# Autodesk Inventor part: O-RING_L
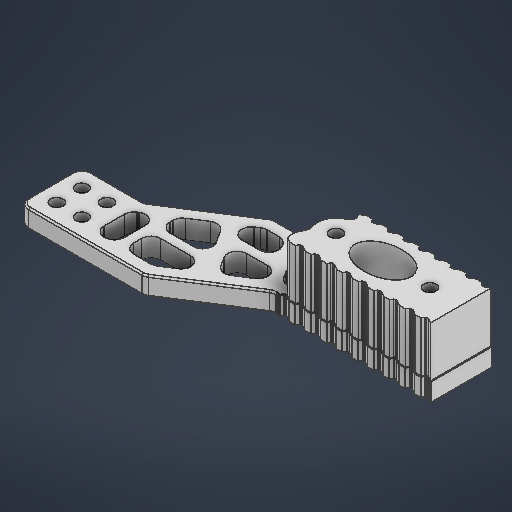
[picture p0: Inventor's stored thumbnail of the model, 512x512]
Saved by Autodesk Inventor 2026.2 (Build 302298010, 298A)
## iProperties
Created: 2026-05
Part Number: O-RING_L
Material: 일반
Document SubType Name: Modeling
Designer: work
Density: 1 g/cm^3
Appearance: 기본값
Author: work
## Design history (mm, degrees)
sketch "스케치1"
  geometry: L1 (0, 22)-(0, -22); L2 (0, -22)-(8, -22); L3 (8, -22)-(8, -30); L4 (8, -30)-(0, -30); L5 (0, -30)-(0, -22); L6 (0, -22)-(8, -30); L7 (8, -22)-(0, -30); L8 (-6, -36)-(14, -36); L9 (14, -36)-(14, -16); L10 (14, -16)-(-6, -16); L11 (-6, -16)-(-6, -36); L12 (-6, -36)-(14, -16); L13 (14, -36)-(-6, -16); L14 (-6, -16)-(-31, 0); L15 (-101, 0)-(-101, -20); L16 (-6, -36)-(-26, -36); L17 (-26, -36)-(-51, -20); L18 (0, 0)-(-31, 0); L19 (-101, -10)-(-15.375, -10); L20 (-101, 0)-(-99.268, -1); L21 (-99.268, -1)-(-98.577, -1); L22 (-98.577, -1)-(-98, 0); L23 (-93.577, -1)-(-93, 0); L24 (-94.268, -1)-(-93.577, -1); L25 (-96, 0)-(-94.268, -1); L26 (-88.577, -1)-(-88, 0); L27 (-89.268, -1)-(-88.577, -1); L28 (-91, 0)-(-89.268, -1); L29 (-83.577, -1)-(-83, 0); L30 (-84.268, -1)-(-83.577, -1); L31 (-86, 0)-(-84.268, -1); L32 (-78.577, -1)-(-78, 0); L33 (-79.268, -1)-(-78.577, -1); L34 (-81, 0)-(-79.268, -1); L35 (-73.577, -1)-(-73, 0); L36 (-74.268, -1)-(-73.577, -1); L37 (-76, 0)-(-74.268, -1); L38 (-68.577, -1)-(-68, 0); L39 (-69.268, -1)-(-68.577, -1); L40 (-71, 0)-(-69.268, -1); L41 (-63.577, -1)-(-63, 0); L42 (-64.268, -1)-(-63.577, -1); L43 (-66, 0)-(-64.268, -1); L44 (-58.577, -1)-(-58, 0); L45 (-59.268, -1)-(-58.577, -1); L46 (-61, 0)-(-59.268, -1); L47 (-53.577, -1)-(-53, 0); L48 (-54.268, -1)-(-53.577, -1); L49 (-56, 0)-(-54.268, -1); L50 (-73.577, -19)-(-73, -20); L51 (-74.268, -19)-(-73.577, -19); L52 (-76, -20)-(-74.268, -19); L53 (-78.577, -19)-(-78, -20); L54 (-79.268, -19)-(-78.577, -19); L55 (-81, -20)-(-79.268, -19); L56 (-83.577, -19)-(-83, -20); L57 (-84.268, -19)-(-83.577, -19); L58 (-86, -20)-(-84.268, -19); L59 (-71, -20)-(-69.268, -19); L60 (-69.268, -19)-(-68.577, -19); L61 (-68.577, -19)-(-68, -20); L62 (-66, -20)-(-64.268, -19); L63 (-64.268, -19)-(-63.577, -19); L64 (-63.577, -19)-(-63, -20)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; C1 r 2 at (-91, -10); C2 r 2 at (-61, -10); 48 further points; 1 other entity
  constraints: 194 end point, 39 symmetric about line, 38 horizontal alignment, 30 parallel, 26 point on line, 11 midpoint, 9 collinear, 9 horizontal, 8 perpendicular, 6 coincident, 4 vertical, 2 centre point, 17 other
  dimensions: "d0" = 44 distance of L1.start L1.end; "d1" = 8 distance of L3.end L4.end; "d2" = 8 distance of L2.end L3.end; "d3" = 6 distance between parallel lines of L2 L10; "d5" = 50 distance from line of L17.end L15; "d6" = 20 distance of L8.start L16.end; "d7" = 25 horizontal distance of L14.end L10.end; "d8" = 20 distance of L15.start L15.end; "d9" = 3 distance of L15.start L22.end; "d10" = 30 deg angle to the sketch x axis of L20; "d11" = 1 distance of the line from the sketch origin of L21; "d14" = 5 distance of L21.end L23.start; "d19" = 4 diameter of C1; "d20" = 4 diameter of C2; "d21" = 30 distance of C1.centre C2.centre; "d22" = 10 distance from line of L15 C1.centre; "d23" = 4 distance between parallel lines of L14 L80; "d24" = 4 distance between parallel lines of L16 L82; "d25" = 3 distance between parallel lines of L90 L86; "d26" = 3 distance between parallel lines of L91 L92; "d27" = 3 distance from line of point (-32.04, -15.735) L89; "d28" = 3 distance between parallel lines of L94 L93; "d29" = 3 distance between parallel lines of L87 L88; "d30" = 3 distance between parallel lines of L95 L96
  node "스케치 - 직사각형 패턴1" dims "d14" = 5, "d17" = 10
extrude "돌출1" new body sketch "스케치1" distance "d31" = 6; taper "d32" = 0 deg
hole "구멍1" sketch "스케치1" diameter "d33" = 4; stored, may be unused: countersink angle "d37" = 90 deg, drill point angle "d39" = 118 deg; dims "d34" = 6, "d35" = 6.2, "d36" = 3, "d38" = 8
sketch "스케치2"
  geometry: C1 r 2 at (61, -10) reference; C2 r 2 at (91, -10) reference; 3 further points
  constraints: 2 coincident
hole "구멍2" sketch "스케치2" at (61, -10), (91, -10) diameter "d40" = 4; stored, may be unused: countersink angle "d44" = 90 deg, drill point angle "d46" = 118 deg; dims "d41" = 6, "d42" = 6.2, "d43" = 3, "d45" = 8
fillet "모깎기1" dims "d47" = 3
fillet "모깎기2" dims "d48" = 0.2
sketch "스케치3"
  geometry: L1 (51.878, -20)-(52.378, -20); L2 (52.378, -20)-(52.378, -19.5); L3 (52.378, -19.5)-(51.878, -19.5); L4 (51.878, -19.5)-(51.878, -20); L5 (51.878, -0.5)-(52.378, -0.5); L6 (52.378, -0.5)-(52.378, 0); L7 (52.378, 0)-(51.878, 0); L8 (51.878, 0)-(51.878, -0.5); L9 (31.878, 0)-(52.885, 0) reference; L10 (52.378, -19.5)-(52.378, -0.5); A1 r 3 centre (51.878, -23) between (51.878, -20) and (50.261, -20.473) reference; 1 further point
  constraints: 18 end point, 4 parallel, 2 horizontal, 2 perpendicular, 1 point on line, 1 vertical
  dimensions: "d49" = 0.5 distance of L3.end L2.end; "d50" = 0.5 distance of L2.end L1.end; "d51" = 0.5 distance of L7.end L6.end; "d52" = 0.5 distance of L6.end L5.end
extrude "돌출2" cut sketch "스케치3" extent not by distance; stored distance "d53" = 0; taper "d54" = 0 deg
chamfer "모따기1" distance "d55" = 0.5; stored, may be unused: second distance "d56" = 2, angle "d57" = 45 deg
chamfer "모따기2" distance "d58" = 0.2; stored, may be unused: second distance "d59" = 2, angle "d60" = 45 deg
node "작업 평면1"
sketch "스케치4"
  geometry: L1 (-37.502, -103.645)-(133.146, -103.645); L2 (133.146, -103.645)-(133.146, 10.321); L3 (133.146, 10.321)-(-37.502, 10.321); L4 (-37.502, 10.321)-(-37.502, -103.645); 1 further point
  constraints: 8 end point, 2 parallel, 1 horizontal, 1 perpendicular
extrude "돌출3" cut sketch "스케치4" extent not by distance; stored distance "d62" = 0; taper "d63" = 0 deg
sketch "스케치5"
  geometry: L1 (63.378, 15.7)-(63.885, 15.7) reference; L2 (63.885, 15.7)-(64.346, 16.5) reference; L3 (64.693, 16.7)-(65.214, 16.7) reference; L4 (65.414, 16.646)-(67.054, 15.7) reference; L5 (67.054, 15.7)-(68.885, 15.7) reference; L6 (68.885, 15.7)-(69.346, 16.5) reference; L7 (69.693, 16.7)-(70.214, 16.7) reference; L8 (70.414, 16.646)-(72.054, 15.7) reference; L9 (72.054, 15.7)-(73.885, 15.7) reference; L10 (73.885, 15.7)-(74.346, 16.5) reference; L11 (74.693, 16.7)-(75.214, 16.7) reference; L12 (75.414, 16.646)-(77.054, 15.7) reference; L13 (77.054, 15.7)-(78.885, 15.7) reference; L14 (78.885, 15.7)-(79.346, 16.5) reference; L15 (79.693, 16.7)-(80.214, 16.7) reference; L16 (80.414, 16.646)-(82.054, 15.7) reference; L17 (82.054, 15.7)-(83.885, 15.7) reference; L18 (83.885, 15.7)-(84.346, 16.5) reference; L19 (84.693, 16.7)-(85.214, 16.7) reference; L20 (85.414, 16.646)-(87.054, 15.7) reference; L21 (87.054, 15.7)-(88.885, 15.7) reference; L22 (88.885, 15.7)-(89.346, 16.5) reference; L23 (89.693, 16.7)-(90.214, 16.7) reference; L24 (90.414, 16.646)-(92.054, 15.7) reference; L25 (92.054, 15.7)-(93.885, 15.7) reference; L26 (93.885, 15.7)-(94.346, 16.5) reference; L27 (94.693, 16.7)-(95.214, 16.7) reference; L28 (95.414, 16.646)-(97.054, 15.7) reference; L29 (97.054, 15.7)-(98.885, 15.7) reference; L30 (98.885, 15.7)-(99.346, 16.5) reference; L31 (99.693, 16.7)-(100.214, 16.7) reference; L32 (100.414, 16.646)-(102.054, 15.7) reference; L33 (102.054, 15.7)-(103.885, 15.7) reference; L34 (103.885, 15.7)-(104.346, 16.5) reference; L35 (104.693, 16.7)-(105.214, 16.7) reference; L36 (105.414, 16.646)-(107.054, 15.7) reference; L37 (107.054, 15.7)-(108.885, 15.7) reference; L38 (108.885, 15.7)-(109.346, 16.5) reference; L39 (109.693, 16.7)-(110.214, 16.7) reference; L40 (110.414, 16.646)-(111.8, 15.846) reference; L41 (111.8, 15.846)-(111.8, 35.154) reference; L42 (111.8, 35.154)-(110.414, 34.354) reference; L43 (110.214, 34.3)-(109.693, 34.3) reference; L44 (109.346, 34.5)-(108.885, 35.3) reference; L45 (108.885, 35.3)-(107.054, 35.3) reference; L46 (107.054, 35.3)-(105.414, 34.354) reference; L47 (105.214, 34.3)-(104.693, 34.3) reference; L48 (104.346, 34.5)-(103.885, 35.3) reference; L49 (103.885, 35.3)-(102.054, 35.3) reference; L50 (102.054, 35.3)-(100.414, 34.354) reference; L51 (100.214, 34.3)-(99.693, 34.3) reference; L52 (99.346, 34.5)-(98.885, 35.3) reference; L53 (98.885, 35.3)-(97.054, 35.3) reference; L54 (97.054, 35.3)-(95.414, 34.354) reference; L55 (95.214, 34.3)-(94.693, 34.3) reference; L56 (94.346, 34.5)-(93.885, 35.3) reference; L57 (93.885, 35.3)-(92.054, 35.3) reference; L58 (92.054, 35.3)-(90.414, 34.354) reference; L59 (90.214, 34.3)-(89.693, 34.3) reference; L60 (89.346, 34.5)-(88.885, 35.3) reference; L61 (88.885, 35.3)-(87.054, 35.3) reference; L62 (87.054, 35.3)-(85.414, 34.354) reference; L63 (85.214, 34.3)-(84.693, 34.3) reference; L64 (84.346, 34.5)-(83.885, 35.3) reference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; C1 r 2 at (11, 13.5) reference; C2 r 2 at (3, 13.5) reference; C3 r 2 at (3, 5.5) reference; C4 r 2 at (11, 5.5) reference; C5 r 10 at (87, 25.5) reference; C6 r 2 at (72, 25.5) reference; C7 r 2 at (102, 25.5) reference; A1 r 0.4 centre (64.693, 16.3) between (64.693, 16.7) and (64.346, 16.5) reference; A2 r 0.4 centre (65.214, 16.3) between (65.414, 16.646) and (65.214, 16.7) reference; A3 r 0.4 centre (69.693, 16.3) between (69.693, 16.7) and (69.346, 16.5) reference; A4 r 0.4 centre (70.214, 16.3) between (70.414, 16.646) and (70.214, 16.7) reference; A5 r 0.4 centre (74.693, 16.3) between (74.693, 16.7) and (74.346, 16.5) reference; A6 r 0.4 centre (75.214, 16.3) between (75.414, 16.646) and (75.214, 16.7) reference; A7 r 0.4 centre (79.693, 16.3) between (79.693, 16.7) and (79.346, 16.5) reference; A8 r 0.4 centre (80.214, 16.3) between (80.414, 16.646) and (80.214, 16.7) reference; A9 r 0.4 centre (84.693, 16.3) between (84.693, 16.7) and (84.346, 16.5) reference; A10 r 0.4 centre (85.214, 16.3) between (85.414, 16.646) and (85.214, 16.7) reference; A11 r 0.4 centre (89.693, 16.3) between (89.693, 16.7) and (89.346, 16.5) reference; A12 r 0.4 centre (90.214, 16.3) between (90.414, 16.646) and (90.214, 16.7) reference; A13 r 0.4 centre (94.693, 16.3) between (94.693, 16.7) and (94.346, 16.5) reference; A14 r 0.4 centre (95.214, 16.3) between (95.414, 16.646) and (95.214, 16.7) reference; A15 r 0.4 centre (99.693, 16.3) between (99.693, 16.7) and (99.346, 16.5) reference; A16 r 0.4 centre (100.214, 16.3) between (100.414, 16.646) and (100.214, 16.7) reference; A17 r 0.4 centre (104.693, 16.3) between (104.693, 16.7) and (104.346, 16.5) reference; A18 r 0.4 centre (105.214, 16.3) between (105.414, 16.646) and (105.214, 16.7) reference; A19 r 0.4 centre (109.693, 16.3) between (109.693, 16.7) and (109.346, 16.5) reference; A20 r 0.4 centre (110.214, 16.3) between (110.414, 16.646) and (110.214, 16.7) reference; A21 r 0.4 centre (110.214, 34.7) between (110.214, 34.3) and (110.414, 34.354) reference; A22 r 0.4 centre (109.693, 34.7) between (109.346, 34.5) and (109.693, 34.3) reference; A23 r 0.4 centre (105.214, 34.7) between (105.214, 34.3) and (105.414, 34.354) reference; A24 r 0.4 centre (104.693, 34.7) between (104.346, 34.5) and (104.693, 34.3) reference; A25 r 0.4 centre (100.214, 34.7) between (100.214, 34.3) and (100.414, 34.354) reference; A26 r 0.4 centre (99.693, 34.7) between (99.346, 34.5) and (99.693, 34.3) reference; A27 r 0.4 centre (95.214, 34.7) between (95.214, 34.3) and (95.414, 34.354) reference; A28 r 0.4 centre (94.693, 34.7) between (94.346, 34.5) and (94.693, 34.3) reference; A29 r 0.4 centre (90.214, 34.7) between (90.214, 34.3) and (90.414, 34.354) reference; A30 r 0.4 centre (89.693, 34.7) between (89.346, 34.5) and (89.693, 34.3) reference; A31 r 0.4 centre (85.214, 34.7) between (85.214, 34.3) and (85.414, 34.354) reference; A32 r 0.4 centre (84.693, 34.7) between (84.346, 34.5) and (84.693, 34.3) reference; A33 r 0.4 centre (80.214, 34.7) between (80.214, 34.3) and (80.414, 34.354) reference; A34 r 0.4 centre (79.693, 34.7) between (79.346, 34.5) and (79.693, 34.3) reference; A35 r 0.4 centre (75.214, 34.7) between (75.214, 34.3) and (75.414, 34.354) reference; A36 r 0.4 centre (74.693, 34.7) between (74.346, 34.5) and (74.693, 34.3) reference; A37 r 0.4 centre (70.214, 34.7) between (70.214, 34.3) and (70.414, 34.354) reference; A38 r 0.4 centre (69.693, 34.7) between (69.346, 34.5) and (69.693, 34.3) reference; A39 r 0.4 centre (65.214, 34.7) between (65.214, 34.3) and (65.414, 34.354) reference; A40 r 0.4 centre (64.693, 34.7) between (64.346, 34.5) and (64.693, 34.3) reference; A41 r 2.5 centre (42.878, 32.5) between (42.878, 35) and (41.53, 34.606) reference; A42 r 3.5 centre (16.122, 22.5) between (16.122, 19) and (18.009, 19.552) reference; A43 r 2.5 centre (0, 16.5) between (0, 19) and (-2.5, 16.5) reference; A44 r 2.5 centre (0, 2.5) between (-2.5, 2.5) and (0, 0) reference; A45 r 2.5 centre (36.122, 2.5) between (36.122, 0) and (37.47, 0.394) reference; A46 r 3.5 centre (62.878, 12.5) between (62.878, 16) and (60.991, 15.448) reference; A47 r 3 centre (29.415, 9.138) between (29.415, 12.138) and (26.415, 9.138) reference; A48 r 3 centre (39.074, 9.138) between (40.691, 6.611) and (39.074, 12.138) reference; A49 r 3 centre (34.952, 6.5) between (34.952, 3.5) and (36.569, 3.973) reference; A50 r 3 centre (29.415, 6.5) between (26.415, 6.5) and (29.415, 3.5) reference; A51 r 3 centre (48.463, 27.691) between (48.463, 24.691) and (50.99, 29.309) reference; A52 r 3 centre (42.785, 27.691) between (41.168, 30.218) and (42.785, 24.691) reference; A53 r 3 centre (44.048, 28.5) between (44.048, 31.5) and (42.431, 31.027) reference; A54 r 3 centre (47.946, 28.5) between (50.473, 30.117) and (47.946, 31.5) reference; A55 r 3 centre (56.282, 32.171) between (53.755, 30.554) and (57.899, 29.644) reference; A56 r 3 centre (55.942, 28.5) between (55.942, 31.5) and (53.755, 30.554) reference; A57 r 3 centre (61.134, 24.59) between (59.516, 27.117) and (58.607, 22.973) reference; A58 r 3 centre (67.242, 28.5) between (67.242, 31.5) and (65.625, 31.027) reference; A59 r 0.2 centre (69.809, 31.3) between (69.88, 31.113) and (69.809, 31.5) reference; A60 r 6 centre (72, 25.5) between (69.88, 31.113) and (66.343, 23.5) reference; A61 r 3 centre (63.515, 22.5) between (63.515, 19.5) and (66.343, 23.5) reference; A62 r 3 centre (62.471, 22.5) between (59.945, 20.883) and (62.471, 19.5) reference; A63 r 3 centre (20.415, 13.375) between (23.415, 13.375) and (18.798, 15.901) reference; A64 r 3 centre (20.415, 6.5) between (20.415, 3.5) and (23.415, 6.5) reference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; 1 further point
  constraints: 5 point on circle, 2 centre point, 2 tangent
extrude "돌출4" join sketch "스케치5" distance "d64" = 16; taper "d65" = 0 deg
node "솔리드1"
mirror "미러1"
node "작업 평면2"
node "투영된 루프1"
feature "A9D066F2-1C7D-4E18-AEED-F7BC21143FA4" dims "d33" = 4, "d34" = 6, "d35" = 6.2, "d36" = 3, "d37" = 90 deg, "d38" = 8, "d39" = 118 deg
